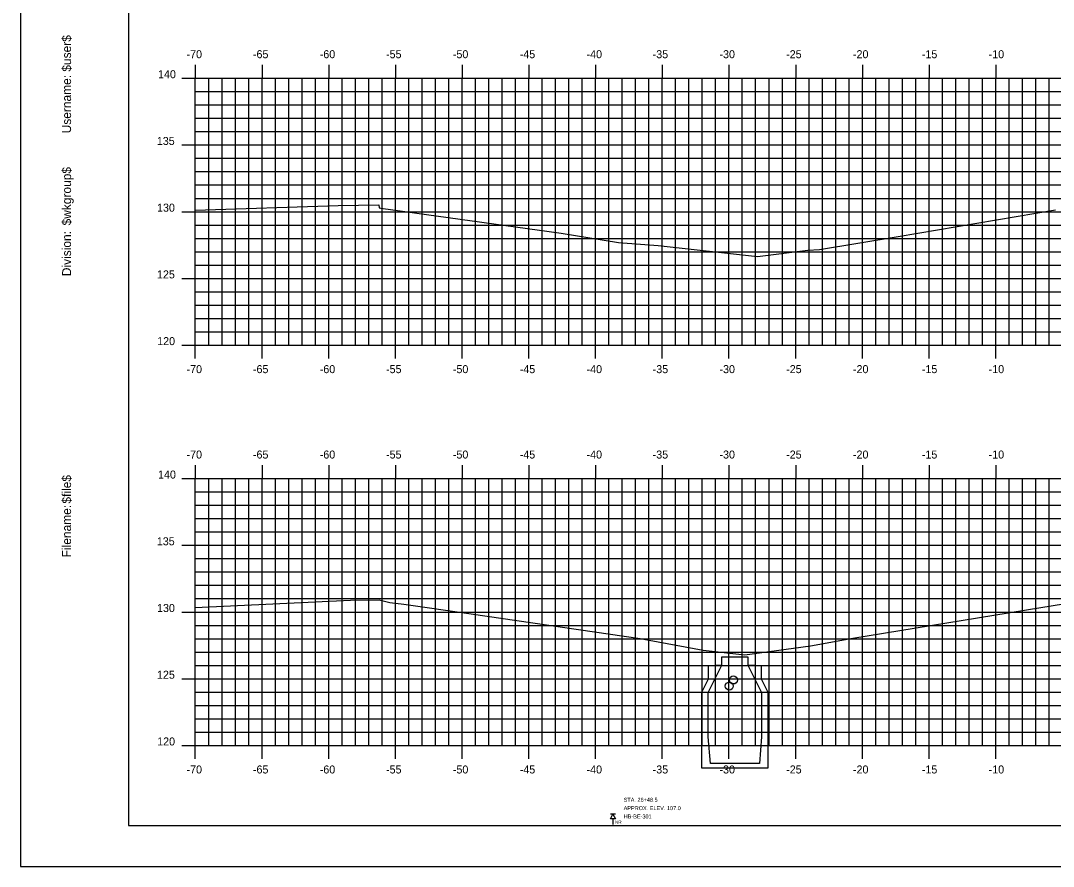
# Model space of a CAD drawing. Extents: x 850851 to 851023, y 365624 to 365734.
# Drawn here: x 850851.4 to 850928.8, y 365624 to 365687.3 of the extents above; entities that cross this region are included whole.
import ezdxf

# ---------------------------------------------------------------- set-up
doc = ezdxf.new("R2010")
doc.units = 0
for name, color, linetype in [('BORDER', 7, 'Continuous'), ('H_V ANNOTATION', 7, 'Continuous'), ('MAJOR', 7, 'Continuous'), ('MINOR', 7, 'Continuous'), ('PLOT BOUNDARY', 7, 'Continuous'), ('ROCKS', 7, 'Continuous'), ('S_Drainage_CB', 7, 'Continuous'), ('S_Drainage_Invert', 7, 'Continuous'), ('S_Roadway_Centerline', 7, 'Continuous')]:
    doc.layers.add(name, color=color, linetype=linetype)

msp = doc.modelspace()

# ---------------------------------------------------------------- linework, layer by layer
at = {"layer": 'BORDER'}
msp.add_lwpolyline([(850859.496, 365627.027), (851019.496, 365627.027), (851019.496, 365732.027), (850859.496, 365732.027)], close=True, dxfattribs=at)
at = {"layer": 'MAJOR'}
for p, q in [((850864.496, 365684.029), (850864.496, 365683.027)), ((850869.496, 365684.029), (850869.496, 365683.027)), ((850874.496, 365684.029), (850874.496, 365683.027)), ((850879.496, 365684.029), (850879.496, 365683.027)), ((850884.496, 365684.029), (850884.496, 365683.027)), ((850889.496, 365684.029), (850889.496, 365683.027)), ((850894.496, 365684.029), (850894.496, 365683.027)), ((850899.496, 365684.029), (850899.496, 365683.027)), ((850904.496, 365684.029), (850904.496, 365683.027)), ((850909.496, 365684.029), (850909.496, 365683.027)), ((850914.496, 365684.029), (850914.496, 365683.027)), ((850919.496, 365684.029), (850919.496, 365683.027)), ((850924.496, 365684.029), (850924.496, 365683.027)), ((850863.494, 365683.027), (850864.496, 365683.027)), ((850864.496, 365683.027), (851004.496, 365683.027)), ((850864.496, 365663.027), (850864.496, 365683.027)), ((850864.496, 365663.027), (850864.496, 365683.027)), ((850864.496, 365683.027), (851004.496, 365683.027)), ((850869.496, 365663.027), (850869.496, 365683.027)), ((850874.496, 365663.027), (850874.496, 365683.027)), ((850879.496, 365663.027), (850879.496, 365683.027)), ((850884.496, 365663.027), (850884.496, 365683.027)), ((850889.496, 365663.027), (850889.496, 365683.027)), ((850894.496, 365663.027), (850894.496, 365683.027)), ((850899.496, 365663.027), (850899.496, 365683.027)), ((850904.496, 365663.027), (850904.496, 365683.027)), ((850909.496, 365663.027), (850909.496, 365683.027)), ((850914.496, 365663.027), (850914.496, 365683.027)), ((850919.496, 365663.027), (850919.496, 365683.027)), ((850924.496, 365663.027), (850924.496, 365683.027)), ((850863.494, 365678.027), (850864.496, 365678.027)), ((850864.496, 365678.027), (851004.496, 365678.027)), ((850863.494, 365673.027), (850864.496, 365673.027)), ((850864.496, 365673.027), (851004.496, 365673.027)), ((850863.494, 365668.027), (850864.496, 365668.027)), ((850864.496, 365668.027), (851004.496, 365668.027)), ((850863.494, 365663.027), (850864.496, 365663.027)), ((850864.496, 365663.027), (851004.496, 365663.027)), ((850864.496, 365663.027), (851004.496, 365663.027)), ((850864.496, 365662.025), (850864.496, 365663.027)), ((850869.496, 365662.025), (850869.496, 365663.027)), ((850874.496, 365662.025), (850874.496, 365663.027)), ((850879.496, 365662.025), (850879.496, 365663.027)), ((850884.496, 365662.025), (850884.496, 365663.027)), ((850889.496, 365662.025), (850889.496, 365663.027)), ((850894.496, 365662.025), (850894.496, 365663.027)), ((850899.496, 365662.025), (850899.496, 365663.027)), ((850904.496, 365662.025), (850904.496, 365663.027)), ((850909.496, 365662.025), (850909.496, 365663.027)), ((850914.496, 365662.025), (850914.496, 365663.027)), ((850919.496, 365662.025), (850919.496, 365663.027)), ((850924.496, 365662.025), (850924.496, 365663.027)), ((850864.496, 365654.029), (850864.496, 365653.027)), ((850869.496, 365654.029), (850869.496, 365653.027)), ((850874.496, 365654.029), (850874.496, 365653.027)), ((850879.496, 365654.029), (850879.496, 365653.027)), ((850884.496, 365654.029), (850884.496, 365653.027)), ((850889.496, 365654.029), (850889.496, 365653.027)), ((850894.496, 365654.029), (850894.496, 365653.027)), ((850899.496, 365654.029), (850899.496, 365653.027)), ((850904.496, 365654.029), (850904.496, 365653.027)), ((850909.496, 365654.029), (850909.496, 365653.027)), ((850914.496, 365654.029), (850914.496, 365653.027)), ((850919.496, 365654.029), (850919.496, 365653.027)), ((850924.496, 365654.029), (850924.496, 365653.027)), ((850863.494, 365653.027), (850864.496, 365653.027)), ((850864.496, 365653.027), (851004.496, 365653.027)), ((850864.496, 365633.027), (850864.496, 365653.027)), ((850864.496, 365633.027), (850864.496, 365653.027)), ((850864.496, 365653.027), (851004.496, 365653.027)), ((850869.496, 365633.027), (850869.496, 365653.027)), ((850874.496, 365633.027), (850874.496, 365653.027)), ((850879.496, 365633.027), (850879.496, 365653.027)), ((850884.496, 365633.027), (850884.496, 365653.027)), ((850889.496, 365633.027), (850889.496, 365653.027)), ((850894.496, 365633.027), (850894.496, 365653.027)), ((850899.496, 365633.027), (850899.496, 365653.027)), ((850904.496, 365633.027), (850904.496, 365653.027)), ((850909.496, 365633.027), (850909.496, 365653.027)), ((850914.496, 365633.027), (850914.496, 365653.027)), ((850919.496, 365633.027), (850919.496, 365653.027)), ((850924.496, 365633.027), (850924.496, 365653.027)), ((850863.494, 365648.027), (850864.496, 365648.027)), ((850864.496, 365648.027), (851004.496, 365648.027)), ((850863.494, 365643.027), (850864.496, 365643.027)), ((850864.496, 365643.027), (851004.496, 365643.027)), ((850863.494, 365638.027), (850864.496, 365638.027)), ((850864.496, 365638.027), (851004.496, 365638.027)), ((850863.494, 365633.027), (850864.496, 365633.027)), ((850864.496, 365633.027), (851004.496, 365633.027)), ((850864.496, 365633.027), (851004.496, 365633.027)), ((850864.496, 365632.025), (850864.496, 365633.027)), ((850869.496, 365632.025), (850869.496, 365633.027)), ((850874.496, 365632.025), (850874.496, 365633.027)), ((850879.496, 365632.025), (850879.496, 365633.027)), ((850884.496, 365632.025), (850884.496, 365633.027)), ((850889.496, 365632.025), (850889.496, 365633.027)), ((850894.496, 365632.025), (850894.496, 365633.027)), ((850899.496, 365632.025), (850899.496, 365633.027)), ((850904.496, 365632.025), (850904.496, 365633.027)), ((850909.496, 365632.025), (850909.496, 365633.027)), ((850914.496, 365632.025), (850914.496, 365633.027)), ((850919.496, 365632.025), (850919.496, 365633.027)), ((850924.496, 365632.025), (850924.496, 365633.027))]:
    msp.add_line(p, q, dxfattribs=at)
at = {"layer": 'MINOR'}
for p, q in [((850865.496, 365663.027), (850865.496, 365683.027)), ((850866.496, 365663.027), (850866.496, 365683.027)), ((850867.496, 365663.027), (850867.496, 365683.027)), ((850868.496, 365663.027), (850868.496, 365683.027)), ((850870.496, 365663.027), (850870.496, 365683.027)), ((850871.496, 365663.027), (850871.496, 365683.027)), ((850872.496, 365663.027), (850872.496, 365683.027)), ((850873.496, 365663.027), (850873.496, 365683.027)), ((850875.496, 365663.027), (850875.496, 365683.027)), ((850876.496, 365663.027), (850876.496, 365683.027)), ((850877.496, 365663.027), (850877.496, 365683.027)), ((850878.496, 365663.027), (850878.496, 365683.027)), ((850880.496, 365663.027), (850880.496, 365683.027)), ((850881.496, 365663.027), (850881.496, 365683.027)), ((850882.496, 365663.027), (850882.496, 365683.027)), ((850883.496, 365663.027), (850883.496, 365683.027)), ((850885.496, 365663.027), (850885.496, 365683.027)), ((850886.496, 365663.027), (850886.496, 365683.027)), ((850887.496, 365663.027), (850887.496, 365683.027)), ((850888.496, 365663.027), (850888.496, 365683.027)), ((850890.496, 365663.027), (850890.496, 365683.027)), ((850891.496, 365663.027), (850891.496, 365683.027)), ((850892.496, 365663.027), (850892.496, 365683.027)), ((850893.496, 365663.027), (850893.496, 365683.027)), ((850895.496, 365663.027), (850895.496, 365683.027)), ((850896.496, 365663.027), (850896.496, 365683.027)), ((850897.496, 365663.027), (850897.496, 365683.027)), ((850898.496, 365663.027), (850898.496, 365683.027)), ((850900.496, 365663.027), (850900.496, 365683.027)), ((850901.496, 365663.027), (850901.496, 365683.027)), ((850902.496, 365663.027), (850902.496, 365683.027)), ((850903.496, 365663.027), (850903.496, 365683.027)), ((850905.496, 365663.027), (850905.496, 365683.027)), ((850906.496, 365663.027), (850906.496, 365683.027)), ((850907.496, 365663.027), (850907.496, 365683.027)), ((850908.496, 365663.027), (850908.496, 365683.027)), ((850910.496, 365663.027), (850910.496, 365683.027)), ((850911.496, 365663.027), (850911.496, 365683.027)), ((850912.496, 365663.027), (850912.496, 365683.027)), ((850913.496, 365663.027), (850913.496, 365683.027)), ((850915.496, 365663.027), (850915.496, 365683.027)), ((850916.496, 365663.027), (850916.496, 365683.027)), ((850917.496, 365663.027), (850917.496, 365683.027)), ((850918.496, 365663.027), (850918.496, 365683.027)), ((850920.496, 365663.027), (850920.496, 365683.027)), ((850921.496, 365663.027), (850921.496, 365683.027)), ((850922.496, 365663.027), (850922.496, 365683.027)), ((850923.496, 365663.027), (850923.496, 365683.027)), ((850925.496, 365663.027), (850925.496, 365683.027)), ((850926.496, 365663.027), (850926.496, 365683.027)), ((850927.496, 365663.027), (850927.496, 365683.027)), ((850928.496, 365663.027), (850928.496, 365683.027)), ((850864.496, 365682.027), (851004.496, 365682.027)), ((850864.496, 365682.027), (850865.498, 365682.027)), ((850864.496, 365681.027), (851004.496, 365681.027)), ((850864.496, 365681.027), (850865.498, 365681.027)), ((850864.496, 365680.027), (851004.496, 365680.027)), ((850864.496, 365680.027), (850865.498, 365680.027)), ((850864.496, 365679.027), (851004.496, 365679.027)), ((850864.496, 365679.027), (850865.498, 365679.027)), ((850864.496, 365677.027), (851004.496, 365677.027)), ((850864.496, 365677.027), (850865.498, 365677.027)), ((850864.496, 365676.027), (851004.496, 365676.027)), ((850864.496, 365676.027), (850865.498, 365676.027)), ((850864.496, 365675.027), (851004.496, 365675.027)), ((850864.496, 365675.027), (850865.498, 365675.027)), ((850864.496, 365674.027), (851004.496, 365674.027)), ((850864.496, 365674.027), (850865.498, 365674.027)), ((850864.496, 365672.027), (851004.496, 365672.027)), ((850864.496, 365672.027), (850865.498, 365672.027)), ((850864.496, 365671.027), (851004.496, 365671.027)), ((850864.496, 365671.027), (850865.498, 365671.027)), ((850864.496, 365670.027), (851004.496, 365670.027)), ((850864.496, 365670.027), (850865.498, 365670.027)), ((850864.496, 365669.027), (851004.496, 365669.027)), ((850864.496, 365669.027), (850865.498, 365669.027)), ((850864.496, 365667.027), (851004.496, 365667.027)), ((850864.496, 365667.027), (850865.498, 365667.027)), ((850864.496, 365666.027), (851004.496, 365666.027)), ((850864.496, 365666.027), (850865.498, 365666.027)), ((850864.496, 365665.027), (851004.496, 365665.027)), ((850864.496, 365665.027), (850865.498, 365665.027)), ((850864.496, 365664.027), (851004.496, 365664.027)), ((850864.496, 365664.027), (850865.498, 365664.027)), ((850865.496, 365633.027), (850865.496, 365653.027)), ((850866.496, 365633.027), (850866.496, 365653.027)), ((850867.496, 365633.027), (850867.496, 365653.027)), ((850868.496, 365633.027), (850868.496, 365653.027)), ((850870.496, 365633.027), (850870.496, 365653.027)), ((850871.496, 365633.027), (850871.496, 365653.027)), ((850872.496, 365633.027), (850872.496, 365653.027)), ((850873.496, 365633.027), (850873.496, 365653.027)), ((850875.496, 365633.027), (850875.496, 365653.027)), ((850876.496, 365633.027), (850876.496, 365653.027)), ((850877.496, 365633.027), (850877.496, 365653.027)), ((850878.496, 365633.027), (850878.496, 365653.027)), ((850880.496, 365633.027), (850880.496, 365653.027)), ((850881.496, 365633.027), (850881.496, 365653.027)), ((850882.496, 365633.027), (850882.496, 365653.027)), ((850883.496, 365633.027), (850883.496, 365653.027)), ((850885.496, 365633.027), (850885.496, 365653.027)), ((850886.496, 365633.027), (850886.496, 365653.027)), ((850887.496, 365633.027), (850887.496, 365653.027)), ((850888.496, 365633.027), (850888.496, 365653.027)), ((850890.496, 365633.027), (850890.496, 365653.027)), ((850891.496, 365633.027), (850891.496, 365653.027)), ((850892.496, 365633.027), (850892.496, 365653.027)), ((850893.496, 365633.027), (850893.496, 365653.027)), ((850895.496, 365633.027), (850895.496, 365653.027)), ((850896.496, 365633.027), (850896.496, 365653.027)), ((850897.496, 365633.027), (850897.496, 365653.027)), ((850898.496, 365633.027), (850898.496, 365653.027)), ((850900.496, 365633.027), (850900.496, 365653.027)), ((850901.496, 365633.027), (850901.496, 365653.027)), ((850902.496, 365633.027), (850902.496, 365653.027)), ((850903.496, 365633.027), (850903.496, 365653.027)), ((850905.496, 365633.027), (850905.496, 365653.027)), ((850906.496, 365633.027), (850906.496, 365653.027)), ((850907.496, 365633.027), (850907.496, 365653.027)), ((850908.496, 365633.027), (850908.496, 365653.027)), ((850910.496, 365633.027), (850910.496, 365653.027)), ((850911.496, 365633.027), (850911.496, 365653.027)), ((850912.496, 365633.027), (850912.496, 365653.027)), ((850913.496, 365633.027), (850913.496, 365653.027)), ((850915.496, 365633.027), (850915.496, 365653.027)), ((850916.496, 365633.027), (850916.496, 365653.027)), ((850917.496, 365633.027), (850917.496, 365653.027)), ((850918.496, 365633.027), (850918.496, 365653.027)), ((850920.496, 365633.027), (850920.496, 365653.027)), ((850921.496, 365633.027), (850921.496, 365653.027)), ((850922.496, 365633.027), (850922.496, 365653.027)), ((850923.496, 365633.027), (850923.496, 365653.027)), ((850925.496, 365633.027), (850925.496, 365653.027)), ((850926.496, 365633.027), (850926.496, 365653.027)), ((850927.496, 365633.027), (850927.496, 365653.027)), ((850928.496, 365633.027), (850928.496, 365653.027)), ((850864.496, 365652.027), (851004.496, 365652.027)), ((850864.496, 365652.027), (850865.498, 365652.027)), ((850864.496, 365651.027), (851004.496, 365651.027)), ((850864.496, 365651.027), (850865.498, 365651.027)), ((850864.496, 365650.027), (851004.496, 365650.027)), ((850864.496, 365650.027), (850865.498, 365650.027)), ((850864.496, 365649.027), (851004.496, 365649.027)), ((850864.496, 365649.027), (850865.498, 365649.027)), ((850864.496, 365647.027), (851004.496, 365647.027)), ((850864.496, 365647.027), (850865.498, 365647.027)), ((850864.496, 365646.027), (851004.496, 365646.027)), ((850864.496, 365646.027), (850865.498, 365646.027)), ((850864.496, 365645.027), (851004.496, 365645.027)), ((850864.496, 365645.027), (850865.498, 365645.027)), ((850864.496, 365644.027), (851004.496, 365644.027)), ((850864.496, 365644.027), (850865.498, 365644.027)), ((850864.496, 365642.027), (851004.496, 365642.027)), ((850864.496, 365642.027), (850865.498, 365642.027)), ((850864.496, 365641.027), (851004.496, 365641.027)), ((850864.496, 365641.027), (850865.498, 365641.027)), ((850864.496, 365640.027), (851004.496, 365640.027)), ((850864.496, 365640.027), (850865.498, 365640.027)), ((850864.496, 365639.027), (851004.496, 365639.027)), ((850864.496, 365639.027), (850865.498, 365639.027)), ((850864.496, 365637.027), (851004.496, 365637.027)), ((850864.496, 365637.027), (850865.498, 365637.027)), ((850864.496, 365636.027), (851004.496, 365636.027)), ((850864.496, 365636.027), (850865.498, 365636.027)), ((850864.496, 365635.027), (851004.496, 365635.027)), ((850864.496, 365635.027), (850865.498, 365635.027)), ((850864.496, 365634.027), (851004.496, 365634.027)), ((850864.496, 365634.027), (850865.498, 365634.027))]:
    msp.add_line(p, q, dxfattribs=at)
at = {"layer": 'PLOT BOUNDARY'}
msp.add_lwpolyline([(850851.403, 365623.968), (851021.403, 365623.968), (851021.403, 365733.968), (850851.403, 365733.968)], close=True, dxfattribs=at)
at = {"layer": 'ROCKS'}
for p, q in [((850895.983, 365627.886), (850895.614, 365627.886)), ((850895.799, 365627.517), (850895.799, 365627.11))]:
    msp.add_line(p, q, dxfattribs=at)
msp.add_lwpolyline([(850895.799, 365627.886), (850895.983, 365627.517), (850895.614, 365627.517)], close=True, dxfattribs=at)
at = {"layer": 'S_Drainage_CB'}
for p, q in [((850903.923, 365638.985), (850902.939, 365638.985)), ((850902.939, 365638.985), (850902.939, 365638.001)), ((850902.939, 365636.984), (850903.923, 365638.985)), ((850906.942, 365638.985), (850905.925, 365638.985)), ((850905.925, 365638.985), (850906.942, 365636.984)), ((850906.942, 365638.001), (850906.942, 365638.985)), ((850902.939, 365638.001), (850902.447, 365636.984)), ((850907.434, 365636.984), (850906.942, 365638.001)), ((850902.447, 365636.984), (850902.447, 365631.341)), ((850902.939, 365633.67), (850902.939, 365636.984)), ((850906.942, 365636.984), (850906.942, 365633.67)), ((850907.434, 365631.341), (850907.434, 365636.984)), ((850903.103, 365631.669), (850902.939, 365633.67)), ((850906.942, 365633.67), (850906.778, 365631.669)), ((850906.778, 365631.669), (850903.103, 365631.669)), ((850902.447, 365631.341), (850907.434, 365631.341))]:
    msp.add_line(p, q, dxfattribs=at)
msp.add_lwpolyline([(850906.417, 365639.027), (850905.925, 365639.027), (850905.925, 365639.65), (850903.923, 365639.65), (850903.923, 365639.027), (850903.431, 365639.027)], dxfattribs=at)
at = {"layer": 'S_Drainage_Invert'}
for centre in [(850904.515, 365637.476), (850904.824, 365637.932)]:
    msp.add_circle(centre, 0.3, dxfattribs=at)
at = {"layer": 'S_Roadway_Centerline'}
for points in [[(850864.496, 365673.129), (850875.193, 365673.486), (850878.25, 365673.538), (850878.264, 365673.303), (850878.4, 365673.28), (850891.912, 365671.408), (850896.205, 365670.726), (850899.195, 365670.492), (850906.634, 365669.658), (850910.407, 365670.134), (850911.277, 365670.191), (850917.187, 365671.156), (850928.976, 365673.159)], [(850864.496, 365643.357), (850876.133, 365643.908), (850878.282, 365643.933), (850879.082, 365643.733), (850880.133, 365643.607), (850885.179, 365642.895), (850897.846, 365641.032), (850902.564, 365640.167), (850905.68, 365639.82), (850910.599, 365640.497), (850913.774, 365641.074), (850927.869, 365643.356), (850930.484, 365643.789)]]:
    msp.add_lwpolyline(points, dxfattribs=at)

# ---------------------------------------------------------------- texts
at = {"layer": 'BORDER'}
for s, p in [('$user$', (850855.181, 365683.518)), ('Username:', (850855.181, 365678.895)), ('$wkgroup$', (850855.181, 365671.996)), ('Division:', (850855.181, 365668.193)), ('$file$', (850855.181, 365651.152)), ('Filename:', (850855.181, 365647.125))]:
    msp.add_text(s, height=0.6696, rotation=90, dxfattribs=at).set_placement(p)
at = {"layer": 'H_V ANNOTATION'}
for s, p in [('-70', (850863.838, 365684.527)), ('-65', (850868.814, 365684.527)), ('-60', (850873.822, 365684.527)), ('-55', (850878.792, 365684.527)), ('-50', (850883.8, 365684.527)), ('-45', (850888.814, 365684.527)), ('-40', (850893.822, 365684.527)), ('-35', (850898.776, 365684.527)), ('-30', (850903.784, 365684.527)), ('-25', (850908.782, 365684.527)), ('-20', (850913.79, 365684.527)), ('-15', (850918.953, 365684.527)), ('-10', (850923.961, 365684.527)), ('140', (850861.701, 365683.027)), ('135', (850861.61, 365678.027)), ('130', (850861.626, 365673.027)), ('125', (850861.621, 365668.027)), ('120', (850861.637, 365663.027)), ('-70', (850863.838, 365660.927)), ('-65', (850868.814, 365660.927)), ('-60', (850873.822, 365660.927)), ('-55', (850878.792, 365660.927)), ('-50', (850883.8, 365660.927)), ('-45', (850888.814, 365660.927)), ('-40', (850893.822, 365660.927)), ('-35', (850898.776, 365660.927)), ('-30', (850903.784, 365660.927)), ('-25', (850908.782, 365660.927)), ('-20', (850913.79, 365660.927)), ('-15', (850918.953, 365660.927)), ('-10', (850923.961, 365660.927)), ('-70', (850863.838, 365654.527)), ('-65', (850868.814, 365654.527)), ('-60', (850873.822, 365654.527)), ('-55', (850878.792, 365654.527)), ('-50', (850883.8, 365654.527)), ('-45', (850888.814, 365654.527)), ('-40', (850893.822, 365654.527)), ('-35', (850898.776, 365654.527)), ('-30', (850903.784, 365654.527)), ('-25', (850908.782, 365654.527)), ('-20', (850913.79, 365654.527)), ('-15', (850918.953, 365654.527)), ('-10', (850923.961, 365654.527)), ('140', (850861.701, 365653.027)), ('135', (850861.61, 365648.027)), ('130', (850861.626, 365643.027)), ('125', (850861.621, 365638.027)), ('120', (850861.637, 365633.027)), ('-70', (850863.838, 365630.927)), ('-65', (850868.814, 365630.927)), ('-60', (850873.822, 365630.927)), ('-55', (850878.792, 365630.927)), ('-50', (850883.8, 365630.927)), ('-45', (850888.814, 365630.927)), ('-40', (850893.822, 365630.927)), ('-35', (850898.776, 365630.927)), ('-30', (850903.784, 365630.927)), ('-25', (850908.782, 365630.927)), ('-20', (850913.79, 365630.927)), ('-15', (850918.953, 365630.927)), ('-10', (850923.961, 365630.927))]:
    msp.add_text(s, height=0.6, dxfattribs=at).set_placement(p)
at = {"layer": 'MAJOR'}
for p in [(850864.492, 365663.027), (850864.492, 365633.027)]:
    msp.add_text('-', height=0.006, dxfattribs=at).set_placement(p)
at = {"layer": 'ROCKS'}
for s, p in [('APPROX. ELEV. 107.0', (850896.602, 365628.179)), ('STA. 26+48.5', (850896.602, 365628.804)), ('HB-BE-301', (850896.602, 365627.554))]:
    msp.add_text(s, height=0.3, rotation=360, dxfattribs=at).set_placement(p)
msp.add_text('NR', height=0.2461, dxfattribs=at).set_placement((850895.956, 365627.154))

doc.saveas('drawing.dxf')
